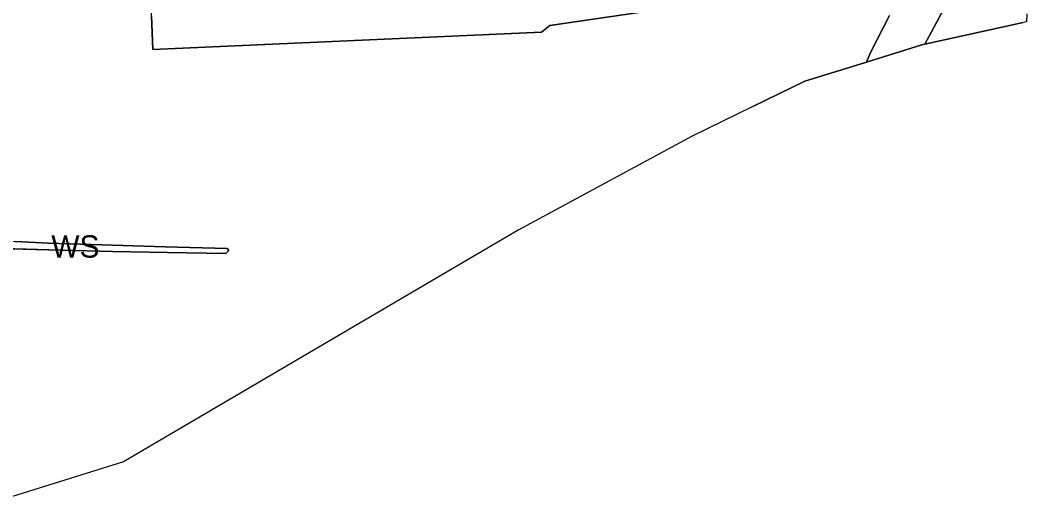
# Model space of a CAD drawing. Extents: x 7417187 to 7419415, y 5539178 to 5540826.
# Drawn here: x 7418734.7 to 7419184.5, y 5539208.7 to 5539426.9 of the extents above; entities that cross this region are included whole.
import ezdxf

# ---------------------------------------------------------------- set-up
doc = ezdxf.new("R2010")
doc.units = 0
doc.layers.add('linie_rozgraniczajace', color=7, linetype='Continuous')
doc.layers.add('oznaczenia_przeznaczen', color=7, linetype='Continuous')

msp = doc.modelspace()

# ---------------------------------------------------------------- linework, layer by layer
at = {"layer": 'linie_rozgraniczajace'}
for p, q in [((7418971.32, 5539424.46), (7419051.94, 5539436.41)), ((7419140.76, 5539419.72), (7419149.51, 5539435.97)), ((7419149.51, 5539435.97), (7419140.76, 5539419.72)), ((7419184.46, 5539429.71), (7419184.31, 5539426.08)), ((7418793.33, 5539428.77), (7418794.01, 5539413.71)), ((7419114.66, 5539412.44), (7419123.03, 5539428.98)), ((7419123.03, 5539428.98), (7419114.66, 5539412.44)), ((7419182.82, 5539425.75), (7419138.91, 5539416.05)), ((7419182.82, 5539425.75), (7419138.91, 5539416.05)), ((7419138.91, 5539416.05), (7419182.82, 5539425.75)), ((7419184.31, 5539426.08), (7419182.82, 5539425.75)), ((7418794.01, 5539413.71), (7418967.53, 5539421.53)), ((7418967.53, 5539421.53), (7418971.32, 5539424.46)), ((7419138.91, 5539416.05), (7419140.76, 5539419.72)), ((7419140.76, 5539419.72), (7419138.91, 5539416.05)), ((7419137.58, 5539415.76), (7419112.83, 5539408.13)), ((7419137.58, 5539415.76), (7419112.83, 5539408.13)), ((7419112.83, 5539408.13), (7419137.58, 5539415.76)), ((7419112.83, 5539408.13), (7419114.66, 5539412.44)), ((7419114.66, 5539412.44), (7419112.83, 5539408.13)), ((7419138.91, 5539416.05), (7419137.58, 5539415.76)), ((7419138.91, 5539416.05), (7419137.58, 5539415.76)), ((7419137.58, 5539415.76), (7419138.91, 5539416.05)), ((7419138.91, 5539416.05), (7419138.91, 5539416.05)), ((7419138.91, 5539416.05), (7419138.91, 5539416.05)), ((7419138.91, 5539416.05), (7419138.91, 5539416.05)), ((7419138.91, 5539416.05), (7419138.91, 5539416.05)), ((7419112.83, 5539408.13), (7419085.26, 5539399.63)), ((7419112.83, 5539408.13), (7419085.26, 5539399.63)), ((7419085.26, 5539399.63), (7419112.83, 5539408.13)), ((7419112.83, 5539408.13), (7419112.83, 5539408.13)), ((7419112.83, 5539408.13), (7419112.83, 5539408.13)), ((7419112.83, 5539408.13), (7419112.83, 5539408.13)), ((7419112.83, 5539408.13), (7419112.83, 5539408.13)), ((7419085.26, 5539399.63), (7419061.95, 5539388.23)), ((7419085.26, 5539399.63), (7419061.95, 5539388.23)), ((7419061.95, 5539388.23), (7419085.26, 5539399.63)), ((7419061.95, 5539388.23), (7419034.9, 5539375.01)), ((7419034.9, 5539375.01), (7418957.15, 5539332.94)), ((7418957.15, 5539332.94), (7418780.77, 5539229.27)), ((7418747.27, 5539327.17), (7418732.47, 5539327.88)), ((7418775.95, 5539326.17), (7418747.27, 5539327.17)), ((7418711.99, 5539325.17), (7418747.48, 5539324.11)), ((7418747.48, 5539324.11), (7418775.99, 5539323.33)), ((7418799.51, 5539325.47), (7418775.95, 5539326.17)), ((7418775.99, 5539323.33), (7418800.43, 5539322.92)), ((7418827.14, 5539324.77), (7418799.51, 5539325.47)), ((7418800.43, 5539322.92), (7418826.63, 5539322.55)), ((7418826.63, 5539322.55), (7418827.95, 5539323.88)), ((7418827.95, 5539323.88), (7418827.14, 5539324.77)), ((7418780.77, 5539229.27), (7418749.84, 5539219.63)), ((7418749.84, 5539219.63), (7418714.84, 5539208.73))]:
    msp.add_line(p, q, dxfattribs=at)
for points in [[(7419080.39, 5539443.66), (7419051.94, 5539436.41), (7418971.32, 5539424.46), (7418967.53, 5539421.53), (7418794.01, 5539413.71), (7418793.33, 5539428.77), (7418792.9, 5539443.79), (7418794.41, 5539443.84), (7418808.32, 5539447.35), (7418824.83, 5539456.31), (7418848.46, 5539469.21), (7418868.88, 5539478.97), (7418878, 5539481.56), (7418905.97, 5539484.62), (7418932.4, 5539485.28), (7418955.96, 5539481.86), (7419031.5, 5539486.94), (7419100.14, 5539494.37), (7419094.9, 5539472.32)], [(7418827.95, 5539323.88), (7418826.63, 5539322.55), (7418800.43, 5539322.92), (7418775.99, 5539323.33), (7418747.48, 5539324.11), (7418711.99, 5539325.17), (7418712.13, 5539328.28), (7418732.47, 5539327.88), (7418747.27, 5539327.17), (7418775.95, 5539326.17), (7418799.51, 5539325.47), (7418827.14, 5539324.77)]]:
    msp.add_lwpolyline(points, close=True, dxfattribs=at)

# ---------------------------------------------------------------- texts
at = {"layer": 'oznaczenia_przeznaczen'}
msp.add_text('WS', height=10, dxfattribs=at).set_placement((7418748.57, 5539320.65))

doc.saveas('drawing.dxf')
